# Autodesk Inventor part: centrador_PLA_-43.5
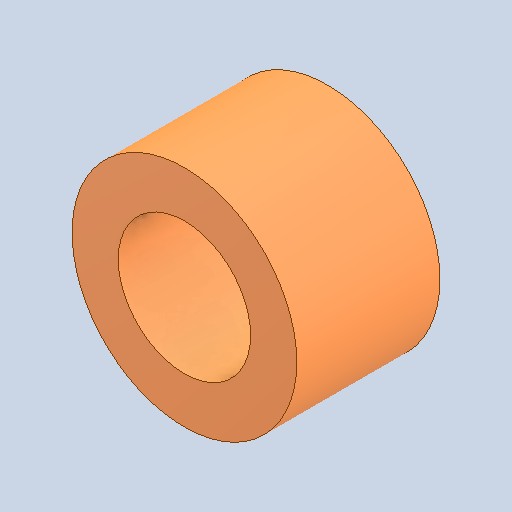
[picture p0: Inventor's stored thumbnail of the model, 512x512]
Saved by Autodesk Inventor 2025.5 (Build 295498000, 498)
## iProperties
Created: 2026-10
Part Number: centrador_PLA_-43.5
Material: Genérico
Document SubType Name: Modeling
Designer: Luis M
Density: 1 g/cm^3
Appearance: Valor por defecto
Author: Luis M
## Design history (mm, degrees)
feature "Base1"
node "Sólido1"
